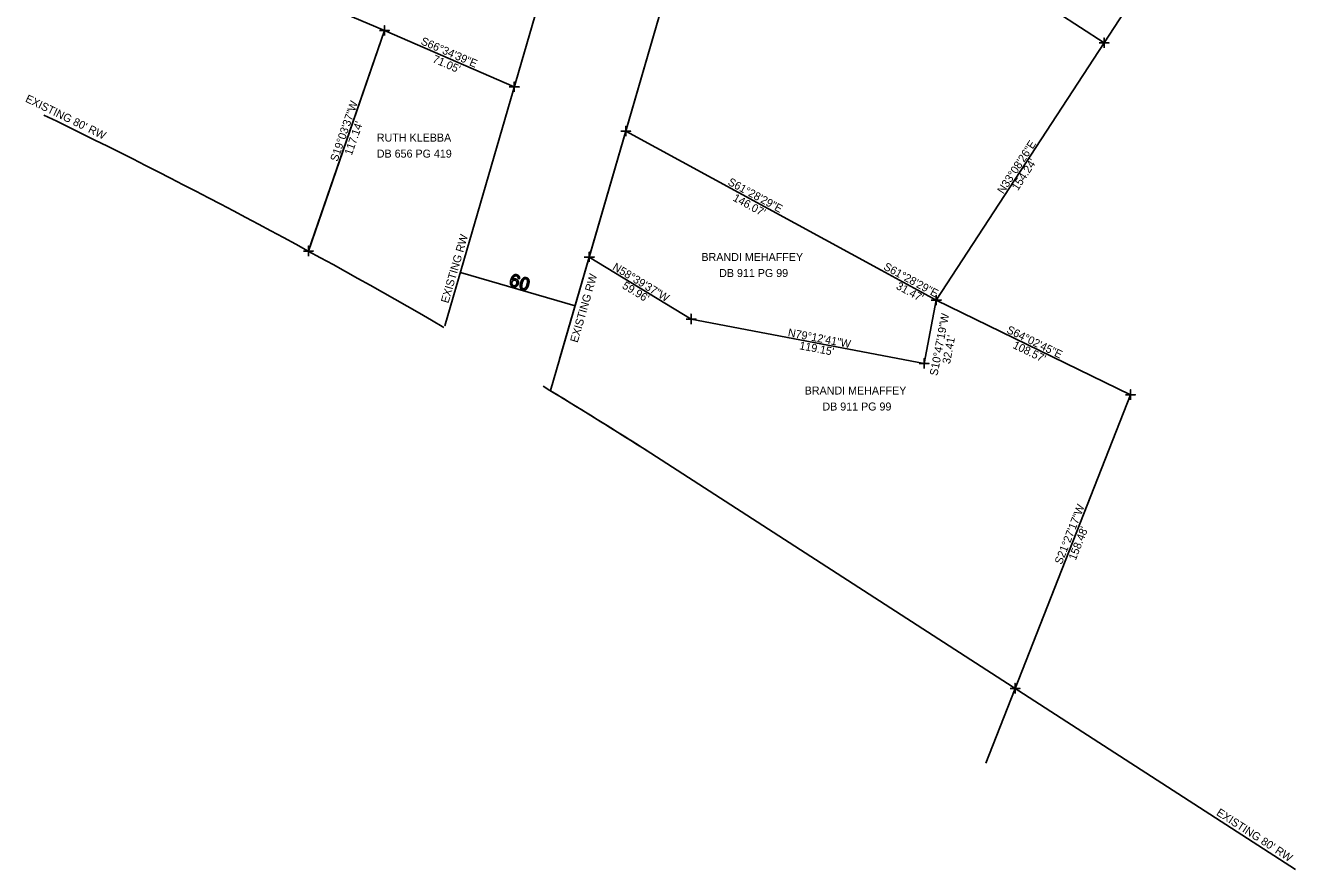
# Model space of a CAD drawing. Extents: x 783966 to 785075, y 667781 to 668938.
# Drawn here: x 783966 to 784604, y 667781 to 668205 of the extents above; entities that cross this region are included whole.
import ezdxf

# ---------------------------------------------------------------- set-up
doc = ezdxf.new("R2010")
doc.units = 0
for name, color, linetype in [('Exist Property Corner CELL', 7, 'Continuous'), ('Exist Property Line', 7, 'Continuous'), ('Exist Property Text', 7, 'Continuous'), ('Exist Right of Way Line', 7, 'Continuous'), ('Exist Right of Way Text', 7, 'Continuous'), ('Exist Right of Way Width CELL', 7, 'Continuous')]:
    doc.layers.add(name, color=color, linetype=linetype)

msp = doc.modelspace()

# ---------------------------------------------------------------- linework, layer by layer
at = {"layer": 'Exist Property Corner CELL'}
for p, q in [((784146.28, 668202.38), (784146.28, 668202.38)), ((784507.78, 668196.18), (784507.78, 668196.18)), ((784211.48, 668174.13), (784211.48, 668174.13)), ((784267.47, 668151.81), (784267.47, 668151.81)), ((784108.03, 668091.66), (784108.03, 668091.66)), ((784249.13, 668088.68), (784249.13, 668088.68)), ((784423.46, 668067.02), (784423.46, 668067.02)), ((784300.35, 668057.49), (784300.35, 668057.49)), ((784417.39, 668035.19), (784417.39, 668035.19)), ((784521.08, 668019.51), (784521.08, 668019.51)), ((784463.11, 667872.01), (784463.11, 667872.01))]:
    msp.add_line(p, q, dxfattribs=at)
for points in [[(784143.78, 668202.38), (784148.78, 668202.38), (784146.28, 668202.38), (784146.28, 668204.88), (784146.28, 668199.88)], [(784505.28, 668196.18), (784510.28, 668196.18), (784507.78, 668196.18), (784507.78, 668198.68), (784507.78, 668193.68)], [(784208.98, 668174.13), (784213.98, 668174.13), (784211.48, 668174.13), (784211.48, 668176.63), (784211.48, 668171.63)], [(784264.97, 668151.81), (784269.97, 668151.81), (784267.47, 668151.81), (784267.47, 668154.31), (784267.47, 668149.31)], [(784105.53, 668091.66), (784110.53, 668091.66), (784108.03, 668091.66), (784108.03, 668094.16), (784108.03, 668089.16)], [(784246.63, 668088.68), (784251.63, 668088.68), (784249.13, 668088.68), (784249.13, 668091.18), (784249.13, 668086.18)], [(784420.96, 668067.02), (784425.96, 668067.02), (784423.46, 668067.02), (784423.46, 668069.52), (784423.46, 668064.52)], [(784297.85, 668057.49), (784302.85, 668057.49), (784300.35, 668057.49), (784300.35, 668059.99), (784300.35, 668054.99)], [(784414.89, 668035.19), (784419.89, 668035.19), (784417.39, 668035.19), (784417.39, 668037.69), (784417.39, 668032.69)], [(784518.58, 668019.51), (784523.58, 668019.51), (784521.08, 668019.51), (784521.08, 668022.01), (784521.08, 668017.01)], [(784460.61, 667872.01), (784465.61, 667872.01), (784463.11, 667872.01), (784463.11, 667874.51), (784463.11, 667869.51)]]:
    msp.add_lwpolyline(points, dxfattribs=at)
at = {"layer": 'Exist Property Line'}
for p, q in [((784507.78, 668196.18), (784581.93, 668309.74)), ((784507.78, 668196.18), (784428.17, 668248.15)), ((784100.27, 668221.96), (784146.28, 668202.38)), ((784146.28, 668202.38), (784107.98, 668091.52)), ((784146.28, 668202.38), (784108.03, 668091.66)), ((784146.28, 668202.38), (784211.48, 668174.13)), ((784423.46, 668067.02), (784507.78, 668196.18)), ((784267.47, 668151.81), (784395.81, 668082.05)), ((784300.35, 668057.49), (784249.13, 668088.68)), ((784395.81, 668082.05), (784423.46, 668067.02)), ((784423.46, 668067.02), (784417.39, 668035.19)), ((784423.46, 668067.02), (784521.08, 668019.51)), ((784417.39, 668035.19), (784300.35, 668057.49)), ((784521.08, 668019.51), (784448.35, 667834.44)), ((784521.08, 668019.51), (784463.11, 667872.01))]:
    msp.add_line(p, q, dxfattribs=at)
at = {"layer": 'Exist Right of Way Line'}
for p, q in [((784176.63, 668054.18), (784235.61, 668257.19)), ((784229.63, 668021.56), (784293.23, 668240.45)), ((784234.25, 668037.44), (784293.23, 668240.45)), ((784604.01, 667781.03), (784280.13, 667990.17))]:
    msp.add_line(p, q, dxfattribs=at)
for start, end in [(59.88518, 64.20809), (57.57308, 58.78431), (57.57308, 58.70288)]:
    msp.add_arc((782663.24, 665445), 3015.33, start, end, dxfattribs=at)
at = {"layer": 'Exist Right of Way Width CELL'}
for p, q in [((784184.4, 668080.93), (784242.02, 668064.19)), ((784210.36, 668076.08), (784210.36, 668076.08)), ((784213.38, 668077.94), (784214.13, 668077.79)), ((784214.73, 668075.81), (784214.73, 668075.81)), ((784215.49, 668075.59), (784215.49, 668075.59))]:
    msp.add_line(p, q, dxfattribs=at)
msp.add_lwpolyline([(784242.02, 668064.19), (784241.77, 668064.27), (784242.02, 668064.32)], dxfattribs=at)
for points in [[(784211.15, 668079.53), (784210.27, 668078.93), (784209.77, 668077.19)], [(784210.58, 668077.26), (784210.85, 668078.16), (784211.19, 668078.59)], [(784212.86, 668079.78), (784211.91, 668080.05), (784211.15, 668079.53)], [(784211.19, 668078.59), (784211.54, 668079.02), (784211.96, 668079.17)], [(784211.96, 668079.17), (784212.28, 668079.29), (784212.64, 668079.19)], [(784212.64, 668079.19), (784213.08, 668079.06), (784213.28, 668078.65)], [(784213.9, 668079.04), (784213.57, 668079.57), (784212.86, 668079.78)], [(784213.28, 668078.65), (784213.41, 668078.4), (784213.38, 668077.94)], [(784214.13, 668077.79), (784214.24, 668078.51), (784213.9, 668079.04)], [(784209.77, 668077.19), (784209.32, 668075.63), (784209.7, 668074.79)], [(784209.7, 668074.79), (784210.09, 668073.94), (784211.01, 668073.67)], [(784210.31, 668075.3), (784210.25, 668075.7), (784210.36, 668076.08)], [(784210.61, 668074.64), (784210.37, 668074.91), (784210.31, 668075.3)], [(784210.36, 668076.08), (784210.53, 668076.66), (784210.98, 668076.92)], [(784211.41, 668077.67), (784210.97, 668077.59), (784210.58, 668077.26)], [(784211.17, 668074.28), (784210.85, 668074.37), (784210.61, 668074.64)], [(784210.98, 668076.92), (784211.44, 668077.17), (784211.93, 668077.03)], [(784211.01, 668073.67), (784211.55, 668073.51), (784212.05, 668073.65)], [(784212.08, 668074.42), (784211.64, 668074.14), (784211.17, 668074.28)], [(784212.27, 668077.63), (784211.85, 668077.76), (784211.41, 668077.67)], [(784211.93, 668077.03), (784212.44, 668076.88), (784212.67, 668076.43)], [(784212.05, 668073.65), (784212.55, 668073.78), (784212.93, 668074.2)], [(784212.71, 668075.35), (784212.52, 668074.7), (784212.08, 668074.42)], [(784213.37, 668076.73), (784213.01, 668077.42), (784212.27, 668077.63)], [(784212.67, 668076.43), (784212.89, 668075.97), (784212.71, 668075.35)], [(784212.93, 668074.2), (784213.32, 668074.61), (784213.48, 668075.18)], [(784213.48, 668075.18), (784213.73, 668076.03), (784213.37, 668076.73)], [(784214.73, 668075.81), (784214.24, 668074.12), (784214.61, 668073.2)], [(784214.61, 668073.2), (784214.93, 668072.43), (784215.79, 668072.18)], [(784215.44, 668077.46), (784215.04, 668076.87), (784214.73, 668075.81)], [(784215.26, 668073.52), (784215.06, 668074.11), (784215.49, 668075.59)], [(784215.97, 668072.78), (784215.46, 668072.93), (784215.26, 668073.52)], [(784216.38, 668078.27), (784215.85, 668078.05), (784215.44, 668077.46)], [(784215.49, 668075.59), (784215.91, 668077.07), (784216.45, 668077.5)], [(784215.79, 668072.18), (784216.45, 668071.99), (784216.99, 668072.22)], [(784216.96, 668073.03), (784216.47, 668072.64), (784215.97, 668072.78)], [(784217.57, 668078.31), (784216.92, 668078.5), (784216.38, 668078.27)], [(784216.45, 668077.5), (784216.88, 668077.85), (784217.39, 668077.7)], [(784217.88, 668074.89), (784217.45, 668073.42), (784216.96, 668073.03)], [(784216.99, 668072.22), (784217.52, 668072.44), (784217.92, 668073.03)], [(784217.39, 668077.7), (784217.9, 668077.55), (784218.11, 668076.96)], [(784218.36, 668077.86), (784218.05, 668078.17), (784217.57, 668078.31)], [(784218.11, 668076.96), (784218.31, 668076.38), (784217.88, 668074.89)], [(784217.92, 668073.03), (784218.33, 668073.62), (784218.64, 668074.67)], [(784218.8, 668077.13), (784218.67, 668077.56), (784218.36, 668077.86)], [(784218.64, 668074.67), (784218.9, 668075.56), (784218.91, 668076.13)], [(784218.91, 668076.13), (784218.93, 668076.69), (784218.8, 668077.13)]]:
    msp.add_open_spline(points, degree=2, dxfattribs=at)

# ---------------------------------------------------------------- texts
at = {"layer": 'Exist Property Text'}
for s, rotation, p in [('S66°34\'39"E', 336.57763, (784164.17, 668195.66)), ("71.05'", 336.57763, (784170.05, 668186.66)), ('S19°03\'37"W', 70.93983, (784122.67, 668136.31)), ("117.14'", 70.93983, (784129.84, 668139.44)), ('N33°08\'26"E', 56.85944, (784457.2, 668120.06)), ("154.24'", 56.85944, (784464.49, 668121.72)), ('S61°28\'29"E', 331.47472, (784318.4, 668125.18)), ("146.07'", 331.47472, (784320.96, 668117.19)), ('N58°39\'37"W', 328.66027, (784260.5, 668082.62)), ('S61°28\'29"E', 331.47472, (784396.65, 668082.65)), ("59.96'", 328.66027, (784265.36, 668073.26)), ("31.47'", 331.47472, (784402.94, 668072.92)), ('S10°47\'19"W', 79.21147, (784424.06, 668028.82)), ('S64°02\'45"E', 334.04587, (784458.48, 668050.8)), ('N79°12\'41"W', 349.21147, (784348.71, 668048.92)), ("32.41'", 79.21147, (784430.38, 668034.75)), ("119.15'", 349.21147, (784354.48, 668042.4)), ("108.57'", 334.04587, (784461.59, 668043.13)), ('S21°27\'17"W', 68.54528, (784486.51, 667933.98)), ("158.48'", 68.54528, (784493.54, 667936.07))]:
    msp.add_text(s, height=4.02, rotation=rotation, dxfattribs=at).set_placement(p)
for s, p in [('RUTH KLEBBA', (784142.46, 668146.64)), ('DB 656 PG 419', (784142.43, 668138.6)), ('BRANDI MEHAFFEY', (784305.51, 668086.68)), ('DB 911 PG 99', (784314.4, 668078.64)), ('BRANDI MEHAFFEY', (784357.39, 668019.63)), ('DB 911 PG 99', (784366.28, 668011.59))]:
    msp.add_text(s, height=4.02, dxfattribs=at).set_placement(p)
at = {"layer": 'Exist Right of Way Text'}
for s, rotation, p in [("EXISTING 80' RW", 334.07932, (783965.49, 668166.84)), ('EXISTING RW', 73.8, (784178.37, 668065.2)), ('EXISTING RW', 73.8, (784243.29, 668045.41)), ("EXISTING 80' RW", 327.14838, (784563.85, 667808.66))]:
    msp.add_text(s, height=4.02, rotation=rotation, dxfattribs=at).set_placement(p)

doc.saveas('drawing.dxf')
